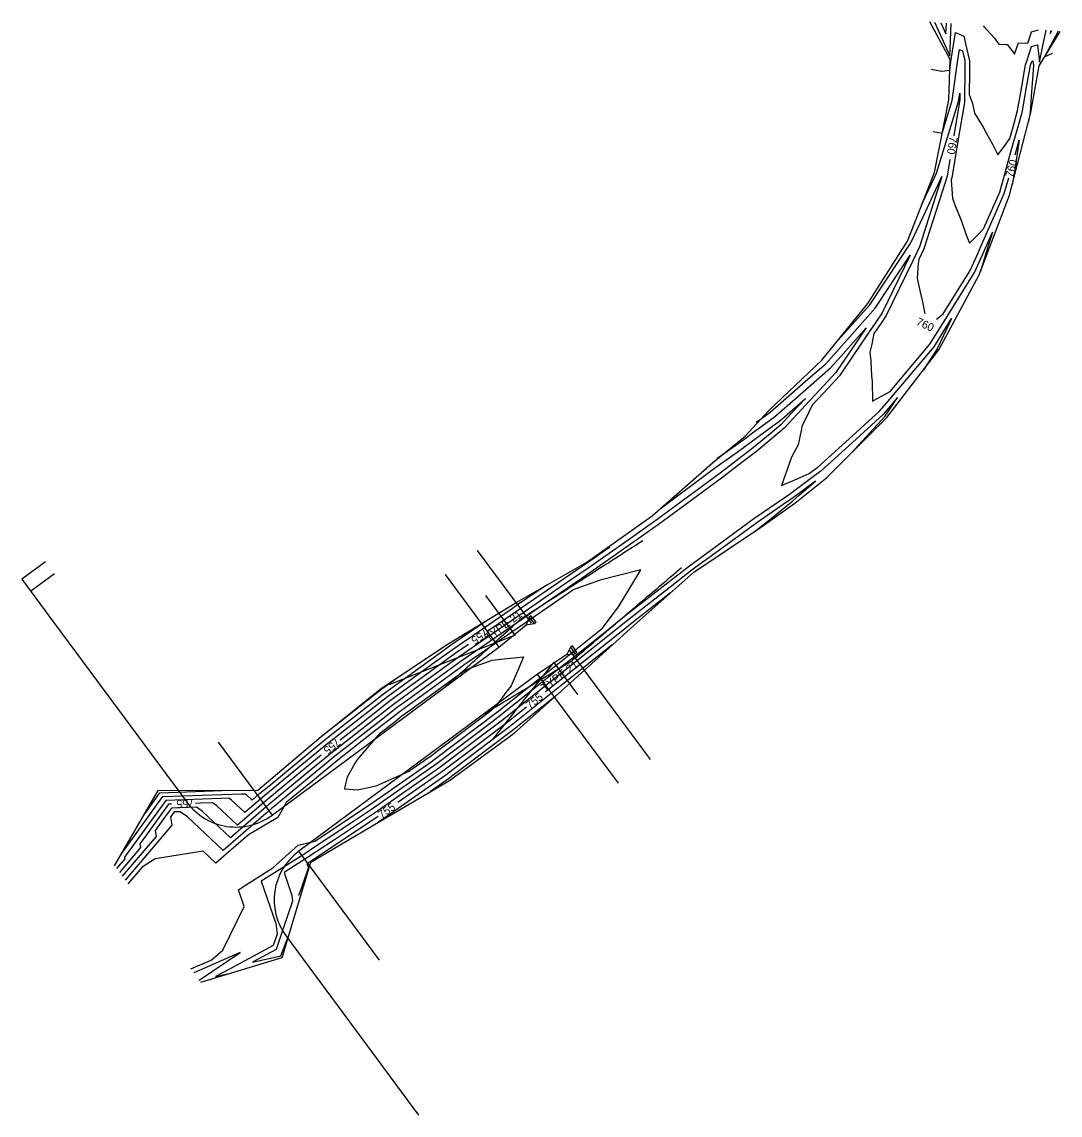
# Model space of a CAD drawing. Extents: x -26 to 1808681, y -24 to 831280.
# Drawn here: x 1808033 to 1808681, y 830597 to 831280 of the extents above; entities that cross this region are included whole.
import ezdxf

# ---------------------------------------------------------------- set-up
doc = ezdxf.new("R2010")
doc.units = 0
for name, color, linetype in [('DESIGN - ROW - Slope Lines', 7, 'Continuous'), ('DESIGN - SCRATCH - User 2', 7, 'Continuous'), ('DESIGN - TRANSPORTATION - GR Special Slope Limit Lines', 7, 'Continuous'), ('DESIGN - TRANSPORTATION - Roadside Barriers', 7, 'Continuous'), ('DESIGN - TRANSPORTATION - Text', 7, 'Continuous'), ('SURVEY - CONTOURS - Index with Text', 7, 'Continuous'), ('SURVEY - CONTOURS - Intermediate with optional Text', 7, 'Continuous')]:
    doc.layers.add(name, color=color, linetype=linetype)

msp = doc.modelspace()

# ---------------------------------------------------------------- linework, layer by layer
at = {"layer": 'DESIGN - ROW - Slope Lines'}
for p, q in [((1808612.58, 831256.72), (1808599.72, 831280.18)), ((1808668.06, 831252.69), (1808681.2, 831274.26)), ((1808611.61, 831231.39), (1808612.58, 831256.72)), ((1808662.95, 831223.56), (1808668.06, 831252.69)), ((1808602.71, 831186.12), (1808611.61, 831231.39)), ((1808649.58, 831171.93), (1808662.95, 831223.56)), ((1808585.76, 831143.17), (1808602.71, 831186.12)), ((1808630.59, 831122.24), (1808649.58, 831171.93)), ((1808561.02, 831104.36), (1808585.76, 831143.17)), ((1808605.37, 831075.32), (1808630.59, 831122.24)), ((1808532.24, 831068.9), (1808561.02, 831104.36)), ((1808572.93, 831033.04), (1808605.37, 831075.32)), ((1808499.28, 831037.54), (1808532.24, 831068.9)), ((1808484.36, 831021.38), (1808499.28, 831037.54)), ((1808535.16, 830995.4), (1808572.93, 831033.04)), ((1808463.95, 831004.87), (1808484.36, 831021.38)), ((1808426.28, 830971.72), (1808463.95, 831004.87)), ((1808515.35, 830979.54), (1808535.16, 830995.4)), ((1808493.9, 830964.43), (1808515.35, 830979.54)), ((1808385.46, 830942.83), (1808426.28, 830971.72)), ((1808452.43, 830936.42), (1808493.9, 830964.43)), ((1808341.73, 830917.87), (1808385.46, 830942.83)), ((1808414.77, 830903.26), (1808452.43, 830936.42)), ((1808298.89, 830891.7), (1808341.73, 830917.87)), ((1808377.58, 830869.45), (1808414.77, 830903.26)), ((1808257.21, 830863.96), (1808298.89, 830891.7)), ((1808340.16, 830835.98), (1808377.58, 830869.45)), ((1808218.13, 830832.72), (1808257.21, 830863.96)), ((1808179.9, 830800.33), (1808218.13, 830832.72)), ((1808299.78, 830806.48), (1808340.16, 830835.98)), ((1808256.39, 830781.06), (1808299.78, 830806.48)), ((1808090.5, 830753.02), (1808117.78, 830800.19)), ((1808117.78, 830800.19), (1808179.9, 830800.33)), ((1808213.14, 830755.44), (1808256.39, 830781.06)), ((1808195.1, 830695.8), (1808213.14, 830755.44)), ((1808144.28, 830680.4), (1808195.1, 830695.8))]:
    msp.add_line(p, q, dxfattribs=at)
at = {"layer": 'DESIGN - SCRATCH - User 2'}
for p, q in [((1808316.99, 830950.03), (1808350.64, 830904.59)), ((1808296.9, 830935.15), (1808330.55, 830889.71)), ((1808322.29, 830921.87), (1808340.59, 830897.15)), ((1808340.66, 830897.2), (1808261.79, 830866.1)), ((1808425.32, 830819.51), (1808374.84, 830887.67)), ((1808364.84, 830880.27), (1808326.33, 830831.82)), ((1808379.82, 830860.04), (1808364.84, 830880.27)), ((1808405.23, 830804.63), (1808354.75, 830872.79)), ((1808155.25, 830830.25), (1808188.9, 830784.81)), ((1808256.05, 830694.15), (1808205.57, 830762.31))]:
    msp.add_line(p, q, dxfattribs=at)
at = {"layer": 'DESIGN - TRANSPORTATION - GR Special Slope Limit Lines'}
for points in [[(1808297.5, 830865.24), (1808298.99, 830866.58), (1808300.49, 830867.92), (1808301.98, 830869.27), (1808303.47, 830870.61), (1808304.97, 830871.95), (1808306.46, 830873.3), (1808307.96, 830874.64), (1808309.45, 830875.98), (1808310.94, 830877.33), (1808312.44, 830878.67), (1808313.93, 830880.01), (1808315.43, 830881.36), (1808316.92, 830882.7), (1808318.41, 830884.04), (1808319.91, 830885.39), (1808321.4, 830886.73), (1808322.9, 830888.07), (1808324.39, 830889.42), (1808325.88, 830890.76), (1808327.38, 830892.1), (1808328.87, 830893.45), (1808330.36, 830894.79), (1808331.86, 830896.13), (1808333.35, 830897.48), (1808334.85, 830898.82), (1808336.34, 830900.16), (1808337.83, 830901.51), (1808339.33, 830902.85), (1808340.82, 830904.19), (1808342.32, 830905.54), (1808343.81, 830906.88), (1808344.56, 830907.55), (1808346.24, 830908.64), (1808347.93, 830909.72), (1808349.62, 830910.8), (1808351.3, 830911.89), (1808352.99, 830912.97), (1808354.68, 830914.05), (1808356.36, 830915.14), (1808358.05, 830916.22), (1808359.74, 830917.3), (1808361.42, 830918.38), (1808363.11, 830919.47), (1808364.8, 830920.55), (1808366.48, 830921.63), (1808368.17, 830922.72), (1808369.86, 830923.8), (1808371.54, 830924.88), (1808373.23, 830925.97), (1808374.92, 830927.05), (1808376.6, 830928.13), (1808378.29, 830929.22), (1808379.97, 830930.3), (1808381.66, 830931.38), (1808383.35, 830932.47), (1808385.03, 830933.55), (1808386.72, 830934.63), (1808388.41, 830935.72), (1808390.09, 830936.8), (1808391.78, 830937.88), (1808393.47, 830938.96), (1808395.15, 830940.05), (1808396.84, 830941.13), (1808398.53, 830942.21), (1808400.21, 830943.3), (1808401.9, 830944.38), (1808403.59, 830945.46), (1808405.27, 830946.55), (1808406.96, 830947.63), (1808408.65, 830948.71), (1808410.33, 830949.8), (1808412.02, 830950.88), (1808413.71, 830951.96), (1808415.39, 830953.05), (1808417.08, 830954.13), (1808418.77, 830955.21), (1808420.45, 830956.29)], [(1808321.7, 830848.32), (1808323.42, 830849.35), (1808325.14, 830850.39), (1808326.86, 830851.43), (1808328.58, 830852.46), (1808330.3, 830853.5), (1808332.02, 830854.54), (1808333.74, 830855.58), (1808335.46, 830856.61), (1808337.18, 830857.65), (1808338.9, 830858.69), (1808340.62, 830859.73), (1808342.34, 830860.76), (1808344.07, 830861.8), (1808345.79, 830862.84), (1808347.51, 830863.87), (1808349.23, 830864.91), (1808350.95, 830865.95), (1808352.67, 830866.99), (1808354.39, 830868.02), (1808356.11, 830869.06), (1808357.83, 830870.1), (1808359.55, 830871.13), (1808361.27, 830872.17), (1808362.99, 830873.21), (1808364.71, 830874.25), (1808366.43, 830875.28), (1808368.15, 830876.32), (1808369.87, 830877.36), (1808371.59, 830878.4), (1808373.32, 830879.43), (1808375.04, 830880.47), (1808375.9, 830880.99), (1808377.42, 830882.29), (1808378.95, 830883.58), (1808380.48, 830884.88), (1808382.01, 830886.18), (1808383.54, 830887.48), (1808385.06, 830888.77), (1808386.59, 830890.07), (1808388.12, 830891.37), (1808389.65, 830892.67), (1808391.18, 830893.96), (1808392.7, 830895.26), (1808394.23, 830896.56), (1808395.76, 830897.85), (1808397.29, 830899.15), (1808398.81, 830900.45), (1808400.34, 830901.75), (1808401.87, 830903.04), (1808403.4, 830904.34), (1808404.93, 830905.64), (1808406.45, 830906.94), (1808407.98, 830908.23), (1808409.51, 830909.53), (1808411.04, 830910.83), (1808412.57, 830912.13), (1808414.09, 830913.42), (1808415.62, 830914.72), (1808417.15, 830916.02), (1808418.68, 830917.32), (1808420.2, 830918.61), (1808421.73, 830919.91), (1808423.26, 830921.21), (1808424.79, 830922.51), (1808426.32, 830923.8), (1808427.84, 830925.1), (1808429.37, 830926.4), (1808430.9, 830927.7), (1808432.43, 830928.99), (1808433.96, 830930.29), (1808435.48, 830931.59), (1808437.01, 830932.89), (1808438.54, 830934.18), (1808440.07, 830935.48), (1808441.6, 830936.78), (1808443.12, 830938.08), (1808444.65, 830939.37)]]:
    msp.add_lwpolyline(points, dxfattribs=at)
at = {"layer": 'DESIGN - TRANSPORTATION - Roadside Barriers'}
for p, q in [((1808032.54, 830932.1), (1808052.99, 830904.48)), ((1808052.99, 830904.48), (1808135.75, 830792.73)), ((1808188.9, 830784.81), (1808330.55, 830889.71)), ((1808354.75, 830872.79), (1808205.57, 830762.31)), ((1808197.64, 830709.16), (1808280.4, 830597.41))]:
    msp.add_line(p, q, dxfattribs=at)
for points in [[(1808349.45, 830908.31), (1808347.53, 830903.53), (1808352.6, 830904.44), (1808353.76, 830905.38), (1808350.61, 830909.26)], [(1808350.61, 830909.26), (1808349.45, 830908.31), (1808352.6, 830904.44), (1808353.76, 830905.38)], [(1808375.26, 830889.59), (1808372.92, 830885.01), (1808378.05, 830885.44), (1808379.3, 830886.28), (1808376.51, 830890.43)], [(1808376.51, 830890.43), (1808375.26, 830889.59), (1808378.05, 830885.44), (1808379.3, 830886.28)]]:
    msp.add_lwpolyline(points, close=True, dxfattribs=at)
for points in [[(1808330.55, 830889.71), (1808330.55, 830889.71), (1808336.21, 830894.32), (1808341.87, 830898.93), (1808347.53, 830903.54)], [(1808372.92, 830885.01), (1808366.86, 830880.93), (1808360.8, 830876.86), (1808354.75, 830872.79), (1808354.75, 830872.79)]]:
    msp.add_lwpolyline(points, dxfattribs=at)
for centre, start, end in [((1808166.29, 830815.35), 216.52307, 306.52307), ((1808228.18, 830731.77), 126.52307, 216.52307)]:
    msp.add_arc(centre, 38, start, end, dxfattribs=at)
at = {"layer": 'DESIGN - TRANSPORTATION - Text'}
for p, q in [((1808047.27, 830943.01), (1808032.54, 830932.1)), ((1808052.85, 830935.48), (1808038.12, 830924.57))]:
    msp.add_line(p, q, dxfattribs=at)
at = {"layer": 'SURVEY - CONTOURS - Index with Text'}
for points in [[(1808595.1, 831166.84), (1808600.89, 831179.06), (1808604.02, 831185.72), (1808614.8, 831220.82), (1808617.76, 831230.45), (1808618.46, 831235.71), (1808618.43, 831232), (1808618.42, 831230.35), (1808614.84, 831208.99)], [(1808653.09, 831197.18), (1808655.62, 831206.23), (1808653, 831189.62), (1808651.2, 831178.18)], [(1808612.34, 831194.2), (1808610.58, 831183.74), (1808609.54, 831180.49), (1808596.05, 831138.37), (1808592.82, 831131.72), (1808592.6, 831129.28), (1808591.95, 831119.92), (1808593.44, 831112.5), (1808595.25, 831105.34), (1808596.64, 831097.9)], [(1808603.88, 831094.57), (1808608.21, 831097.86), (1808625.07, 831124.82), (1808629.12, 831133.98), (1808633.18, 831143.19), (1808640.48, 831159.71), (1808646.3, 831172.92), (1808649.05, 831182.73)], [(1808393.14, 830948.26), (1808399.83, 830952.19), (1808385.82, 830942.34), (1808382.69, 830940.19), (1808344.57, 830914.03), (1808330.37, 830904.28), (1808323.91, 830899.83)], [(1808437.87, 830923.61), (1808413.67, 830904.73), (1808405.83, 830898.48), (1808374.56, 830873.53), (1808360.54, 830862.36), (1808359.48, 830861.52)], [(1808311.55, 830891.33), (1808303.34, 830885.69), (1808285.61, 830872.83), (1808262.86, 830856.34), (1808242.54, 830840.42), (1808231.34, 830831.64)], [(1808347.75, 830852.17), (1808335.43, 830842.36), (1808313.05, 830825.43), (1808295.55, 830812.2), (1808267.49, 830792.57)], [(1808219.61, 830822.3), (1808204.3, 830809.66), (1808184.86, 830793.63), (1808167.32, 830778.45), (1808154.35, 830790.68), (1808151.72, 830792.49), (1808144.04, 830792.23), (1808140.99, 830792.12)], [(1808126, 830791.61), (1808124.18, 830791.55), (1808110.38, 830772.43), (1808106.29, 830766.78), (1808106.72, 830764.53), (1808093.46, 830749.02)], [(1808255.19, 830783.97), (1808254.56, 830783.53), (1808215.39, 830757.58), (1808212.82, 830755.88), (1808210.58, 830754.46), (1808211.33, 830752.26), (1808211.4, 830751.72), (1808210.51, 830749.12), (1808205.59, 830734.76), (1808211.04, 830748.49)]]:
    msp.add_lwpolyline(points, dxfattribs=at)
at = {"layer": 'SURVEY - CONTOURS - Intermediate with optional Text'}
for points in [[(1808602.75, 831279.96), (1808612.2, 831258.9), (1808612.41, 831263.24), (1808613.14, 831279.2)], [(1808606.74, 831279.67), (1808609.84, 831272.76), (1808610.15, 831279.42)], [(1808633.21, 831277.74), (1808633.53, 831277.46), (1808633.57, 831277.33), (1808633.59, 831277.31), (1808639.91, 831270.11), (1808642.82, 831266.29), (1808648.13, 831266.11), (1808652.41, 831260.33), (1808652.72, 831259.92), (1808655.13, 831267.07), (1808660.96, 831266.84), (1808662.83, 831272.59), (1808663.26, 831273.94), (1808667.65, 831275.24)], [(1808600.66, 831250.63), (1808607.22, 831249.38), (1808612.32, 831250.08), (1808613.21, 831256.67), (1808615.88, 831273.63), (1808620.94, 831271.32), (1808622.28, 831265.68), (1808624.63, 831255.84), (1808624.56, 831249.12), (1808624.41, 831234.9), (1808625.03, 831233.18), (1808626.4, 831229.13), (1808627.5, 831224.27), (1808627.73, 831223.09), (1808633.09, 831214.32), (1808635.09, 831210.4), (1808639.03, 831203.71), (1808642.3, 831197.08), (1808645.72, 831201.69), (1808649.75, 831207.42), (1808652.17, 831216.02), (1808654.63, 831224.83), (1808656.82, 831237.26), (1808659.63, 831253.3), (1808660.41, 831255.72), (1808663.34, 831264.73), (1808667.04, 831265.83), (1808668.23, 831255.1), (1808670.34, 831265.13), (1808672.4, 831274.9)], [(1808679.94, 831274.35), (1808671.48, 831258.31), (1808676.32, 831260.7)], [(1808675.39, 831274.68), (1808675.01, 831272.85), (1808675.95, 831274.64)], [(1808601.9, 831211.7), (1808607.53, 831210.63), (1808613.81, 831231.05), (1808615.4, 831242.97), (1808617.2, 831256.38), (1808618.23, 831262.98), (1808620.2, 831262.08), (1808621.63, 831256.06), (1808621.57, 831249.01), (1808621.41, 831232.86), (1808621.39, 831230.87), (1808621.38, 831229.9), (1808617.53, 831206.97), (1808613.45, 831182.87), (1808613.1, 831181.78), (1808613.12, 831181.4), (1808613.96, 831170.06), (1808615.62, 831165.38), (1808619.36, 831156.28), (1808622.46, 831147.18), (1808624.54, 831141.89), (1808629.51, 831146.9), (1808633.36, 831150.98), (1808638.34, 831162.25), (1808643.43, 831173.79), (1808647.06, 831186.73), (1808650.7, 831199.74), (1808654.54, 831213.43), (1808657.6, 831224.38), (1808659.84, 831237.16), (1808662.62, 831253.09), (1808663.41, 831255.52), (1808664.2, 831255.75), (1808664.51, 831252.95), (1808663.11, 831233.55), (1808662.4, 831223.65), (1808661.52, 831218.04)], [(1808540.64, 831079.25), (1808558.34, 831099.08), (1808562.29, 831103.54), (1808581.37, 831132.35), (1808587.86, 831142.19), (1808595.57, 831158.49), (1808607.37, 831183.54), (1808593.33, 831139.63), (1808589.14, 831131), (1808572.52, 831096.84), (1808568.88, 831091.46), (1808564.87, 831085.55), (1808563.49, 831078.94), (1808562.28, 831073.92), (1808562.96, 831068.26), (1808563.35, 831058.87), (1808563.67, 831055.78), (1808564.03, 831043.31), (1808564.55, 831043.61), (1808574.94, 831049.4), (1808599.89, 831078.91), (1808606.91, 831090.14), (1808627.78, 831123.55), (1808632.66, 831134.59), (1808638.95, 831148.86), (1808636.32, 831140.32), (1808631.38, 831124.33)], [(1808491.25, 831030.11), (1808494.57, 831032.44), (1808500.14, 831036.53), (1808525.31, 831058.41), (1808534.77, 831066.67), (1808551.24, 831085.13), (1808565.63, 831101.34), (1808573.8, 831113.67), (1808587.45, 831134.38), (1808570.01, 831098.48), (1808565.99, 831092.53), (1808561.15, 831085.4), (1808551.97, 831071.84), (1808543.34, 831059.12), (1808536.17, 831051.42), (1808526.19, 831040.71), (1808523.98, 831035.97), (1808519.76, 831027.4), (1808519.41, 831025.03), (1808517.53, 831016.1), (1808513.37, 831008.34), (1808507.09, 830990.69), (1808507.03, 830990.6), (1808507.06, 830990.57), (1808507.16, 830990.61), (1808516.97, 830994.77), (1808524.48, 830998.02), (1808528.43, 831000.96), (1808529.65, 831001.87), (1808549.38, 831019.75), (1808568.4, 831037.02), (1808572.52, 831041.9), (1808602.4, 831077.27), (1808613.39, 831094.87), (1808610.51, 831088.77), (1808604.43, 831075.94), (1808595.56, 831062.54)], [(1808466.91, 831007.61), (1808470.06, 831009.81), (1808485.04, 831020.47), (1808488.21, 831022.8), (1808502.73, 831033.49), (1808517.1, 831045.98), (1808537.78, 831064.03), (1808544.15, 831071.17), (1808560, 831089.03), (1808549.86, 831074.04), (1808541.09, 831061.1), (1808533.56, 831053), (1808522.13, 831040.74), (1808514.45, 831032.5), (1808508.77, 831026.4), (1808502.13, 831020.83), (1808491.43, 831011.85), (1808482.42, 831004.97), (1808470.57, 830995.93), (1808445.82, 830977.7), (1808430.31, 830966.28), (1808401.26, 830945.86), (1808389.39, 830937.52), (1808385.22, 830934.66), (1808378.57, 830930.09), (1808355.05, 830913.95), (1808348.14, 830909.21), (1808316.1, 830887.19), (1808306.91, 830880.87), (1808274.95, 830857.69), (1808266.43, 830851.52), (1808258.82, 830845.55), (1808227.06, 830820.67), (1808221.85, 830816.37), (1808194.07, 830793.46), (1808191.12, 830791.03), (1808188.43, 830788.81), (1808184.87, 830785.73), (1808158.27, 830762.71), (1808135.97, 830783.73), (1808131.45, 830786.85), (1808127.76, 830786.73), (1808125.35, 830783.4), (1808126.29, 830778.42), (1808097.03, 830744.2)], [(1808431.24, 830976.08), (1808466.04, 831002.04), (1808479.36, 831011.51), (1808487.42, 831017.25), (1808501.72, 831027.79), (1808505.32, 831030.44), (1808508.89, 831033.54), (1808522.01, 831045), (1808512.98, 831035.29), (1808506.82, 831028.68), (1808500.04, 831022.99), (1808489.64, 831014.26), (1808480.53, 831007.31), (1808468.78, 830998.34), (1808444.4, 830980.38), (1808428.53, 830968.69), (1808411.27, 830956.56), (1808387.61, 830939.93), (1808368.87, 830927.07), (1808346.35, 830911.62), (1808323.24, 830895.73), (1808305.12, 830883.28), (1808280.28, 830865.26), (1808264.64, 830853.93), (1808250.68, 830842.99), (1808225.27, 830823.08), (1808213.07, 830813.02), (1808186.65, 830791.22), (1808162.8, 830770.58), (1808145.16, 830787.2), (1808141.58, 830789.67), (1808131.14, 830789.31), (1808125.97, 830789.14), (1808122.37, 830784.16), (1808115.82, 830775.09), (1808116.51, 830771.47), (1808095.25, 830746.61)], [(1808550.95, 831011.13), (1808562.07, 831023.26), (1808571.87, 831033.97), (1808579.58, 831045.61), (1808570.65, 831035.04), (1808551.39, 831017.55), (1808531.6, 830999.58), (1808528.79, 830997.49), (1808517.15, 830988.84), (1808512.85, 830985.65), (1808511.55, 830984.68), (1808508.72, 830982.73), (1808489.93, 830969.79), (1808470, 830955.24), (1808449.54, 830940.31), (1808433.1, 830927.49), (1808410.1, 830909.56), (1808399.84, 830901.37), (1808376.66, 830882.87), (1808370.99, 830878.35), (1808340.4, 830853.98), (1808331.86, 830847.18), (1808324.25, 830841.42), (1808291.98, 830817.02), (1808280.35, 830808.89), (1808250.99, 830788.35), (1808240.36, 830781.31), (1808215.35, 830764.74), (1808209.25, 830760.7), (1808205.27, 830758.19), (1808182.12, 830743.62), (1808191.18, 830717.02), (1808192.02, 830710.41), (1808189.57, 830703.26), (1808161.84, 830688.45), (1808153.41, 830683.95), (1808163.74, 830686.29)], [(1808491.1, 830962.54), (1808493.79, 830964.57), (1808497.52, 830967.6), (1808514.16, 830981.15), (1808518.2, 830984.65), (1808528.29, 830993.39), (1808516.19, 830984.39), (1808513.33, 830982.27), (1808508.11, 830978.67), (1808491.71, 830967.38), (1808469.97, 830951.51), (1808451.33, 830937.9), (1808434.69, 830924.93), (1808411.89, 830907.14), (1808391.25, 830890.68), (1808372.78, 830875.94), (1808350.47, 830858.17), (1808333.65, 830844.77), (1808318.65, 830833.43), (1808293.76, 830814.61), (1808272.43, 830799.68), (1808252.78, 830785.94), (1808227.88, 830769.44), (1808211.04, 830758.29), (1808196.35, 830749.04), (1808201.25, 830734.64), (1808201.71, 830731.07), (1808195.88, 830714.06), (1808191.35, 830700.85), (1808176.59, 830692.97), (1808194.23, 830696.97), (1808199.37, 830709.9)], [(1808138.14, 830688.69), (1808150.78, 830694.2), (1808158.15, 830700.44), (1808171.46, 830727.72), (1808167.89, 830738.21), (1808172.21, 830740.93), (1808189.43, 830751.76), (1808205.24, 830766.11), (1808215.6, 830768.49), (1808249.2, 830790.76), (1808256.62, 830795.94), (1808272.32, 830806.93), (1808288.28, 830818.09), (1808290.19, 830819.43), (1808329.85, 830849.42), (1808330.08, 830849.59), (1808330.33, 830849.79), (1808332.08, 830851.19), (1808355.09, 830869.52), (1808369.21, 830880.76), (1808395.28, 830901.57), (1808405.7, 830915.5), (1808414.76, 830930.61), (1808419.14, 830937.9), (1808393.79, 830931.57), (1808381.52, 830927.15), (1808377.43, 830925.67), (1808360.52, 830914.07), (1808349.92, 830906.8), (1808310.81, 830879.91), (1808308.96, 830878.64), (1808308.69, 830878.46), (1808269.62, 830850.12), (1808268.22, 830849.1), (1808266.96, 830848.12), (1808251.04, 830835.65), (1808235.96, 830823.83), (1808228.84, 830818.26), (1808214.01, 830806.02), (1808197.74, 830792.6), (1808196.75, 830790.89), (1808192.44, 830783.39), (1808174.1, 830772.45), (1808158.72, 830759.14), (1808153.75, 830754.84), (1808145.87, 830762.27), (1808115.9, 830757.5), (1808107.77, 830752.26), (1808098.82, 830741.79)], [(1808360.32, 830928.48), (1808342.78, 830916.44), (1808337.51, 830912.82), (1808301.55, 830888.1), (1808290.94, 830880.41), (1808261.07, 830858.75), (1808234.4, 830837.85), (1808221.7, 830827.9), (1808195.52, 830806.31), (1808183.08, 830796.04), (1808171.84, 830786.32), (1808163.53, 830794.15), (1808161.85, 830795.31), (1808156.93, 830795.14), (1808122.4, 830793.96), (1808098.38, 830760.71), (1808096.76, 830758.47), (1808096.93, 830757.58), (1808091.67, 830751.43)], [(1808095.35, 830761.41), (1808120.61, 830796.37), (1808169.83, 830798.06), (1808171.98, 830798.13), (1808172.72, 830797.62), (1808176.36, 830794.19), (1808181.29, 830798.45), (1808186.75, 830802.95), (1808219.91, 830830.31), (1808226.26, 830835.28), (1808259.29, 830861.16), (1808296.27, 830887.98), (1808299.77, 830890.51), (1808322.28, 830905.99)], [(1808401.41, 830891.12), (1808376.35, 830871.12), (1808370.61, 830866.55), (1808337.22, 830839.95), (1808307.45, 830817.43), (1808297.33, 830809.79), (1808256.57, 830781.28), (1808256.35, 830781.12), (1808255.19, 830780.35)], [(1808283.91, 830818.7), (1808274.39, 830812.04), (1808264.92, 830807.86), (1808253.63, 830802.89), (1808250.09, 830802.12), (1808242.08, 830800.39), (1808234.3, 830801.01), (1808234.61, 830802.43), (1808235.97, 830808.63), (1808239.96, 830815.79), (1808241.73, 830818.96), (1808249.78, 830828.31), (1808256.54, 830836.15), (1808265.68, 830843.31), (1808270, 830846.69), (1808275.56, 830850.73), (1808307.48, 830873.87), (1808309.2, 830874.94), (1808310.64, 830875.83), (1808326.26, 830881.56), (1808335.76, 830882.57), (1808345.89, 830883.65), (1808342.09, 830874.71), (1808338.17, 830865.49), (1808335.62, 830862.12), (1808328.13, 830852.22), (1808326.86, 830851.1), (1808325.33, 830849.76), (1808293.89, 830825.98), (1808288.41, 830821.84), (1808283.91, 830818.7)], [(1808218.67, 830833.15), (1808257.5, 830863.57), (1808267.31, 830870.68)], [(1808365.5, 830858.65), (1808339, 830837.53), (1808301.85, 830809.44), (1808299.12, 830807.37), (1808287.88, 830799.51)], [(1808109.49, 830785.86), (1808118.83, 830798.78), (1808163.01, 830800.3)], [(1808143.35, 830681.66), (1808168.92, 830698.93), (1808139.93, 830686.27)]]:
    msp.add_lwpolyline(points, dxfattribs=at)

# ---------------------------------------------------------------- texts
at = {"layer": 'DESIGN - TRANSPORTATION - Text'}
for p in [(1808324.07, 830893.17), (1808359.22, 830861.81)]:
    msp.add_text('TYPE 21', height=5, rotation=36.52307, dxfattribs=at).set_placement(p)
at = {"layer": 'SURVEY - CONTOURS - Index with Text'}
for s, rotation, p in [('760', 260.43431, (1808612.28, 831208.86)), ('760', 74.38147, (1808651.61, 831182.59)), ('760', 335.31057, (1808590.79, 831091.18)), ('755', 214.50383, (1808321.86, 830901.45)), ('755', 38.54239, (1808349.91, 830850.7)), ('755', 218.55942, (1808229.14, 830833.17)), ('755', 181.96398, (1808140.14, 830794.6)), ('755', 34.96998, (1808257.26, 830782.36))]:
    msp.add_text(s, height=5, rotation=rotation, dxfattribs=at).set_placement(p)

doc.saveas('drawing.dxf')
